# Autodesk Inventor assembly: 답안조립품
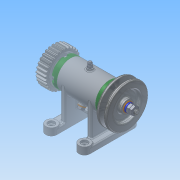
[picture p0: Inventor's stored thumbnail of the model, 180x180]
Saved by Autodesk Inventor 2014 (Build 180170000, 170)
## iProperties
Created: 2015-11
Part Number: 답안조립품
Document SubType Name: Assembly
Designer: net
Author: net
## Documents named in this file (16)
- C:\Users\net\Desktop\451109V1005\답안조립품.iam
- C:\Users\net\Desktop\451109V1005\V벨트풀리.ipt
- C:\Users\net\Desktop\451109V1005\너트 M 8.ipt
- C:\Users\net\Desktop\451109V1005\니플 M 6 x 0.75.ipt
- C:\Users\net\Desktop\451109V1005\베어링 15 x 32 x 9.ipt
- C:\Users\net\Desktop\451109V1005\본체.ipt
- C:\Users\net\Desktop\451109V1005\볼트 M 6 x 8.ipt
- C:\Users\net\Desktop\451109V1005\볼트 M4 x 12.ipt
- C:\Users\net\Desktop\451109V1005\스퍼기어.ipt
- C:\Users\net\Desktop\451109V1005\스프링와셔 8.ipt
- C:\Users\net\Desktop\451109V1005\오일 실 15 25 7.ipt
- C:\Users\net\Desktop\451109V1005\와셔 6x11.5.ipt
- C:\Users\net\Desktop\451109V1005\와셔 8x17.ipt
- C:\Users\net\Desktop\451109V1005\축.ipt
- C:\Users\net\Desktop\451109V1005\커버.ipt
- C:\Users\net\Desktop\451109V1005\키 3 x 3 x 12.ipt
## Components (11 placed, 3 different names)
1. V벨트풀리:1
2. KS B 2023 6002 - 15 x 32 x 9:1
3. ISO 4762 M4 x 12:1
4. KS B 2023 6002 - 15 x 32 x 9:2
5. ISO 4762 M4 x 12:2
6. ISO 4762 M4 x 12:3
7. ISO 4762 M4 x 12:4
8. ISO 4762 M4 x 12:5
9. ISO 4762 M4 x 12:6
10. ISO 4762 M4 x 12:7
11. ISO 4762 M4 x 12:8
